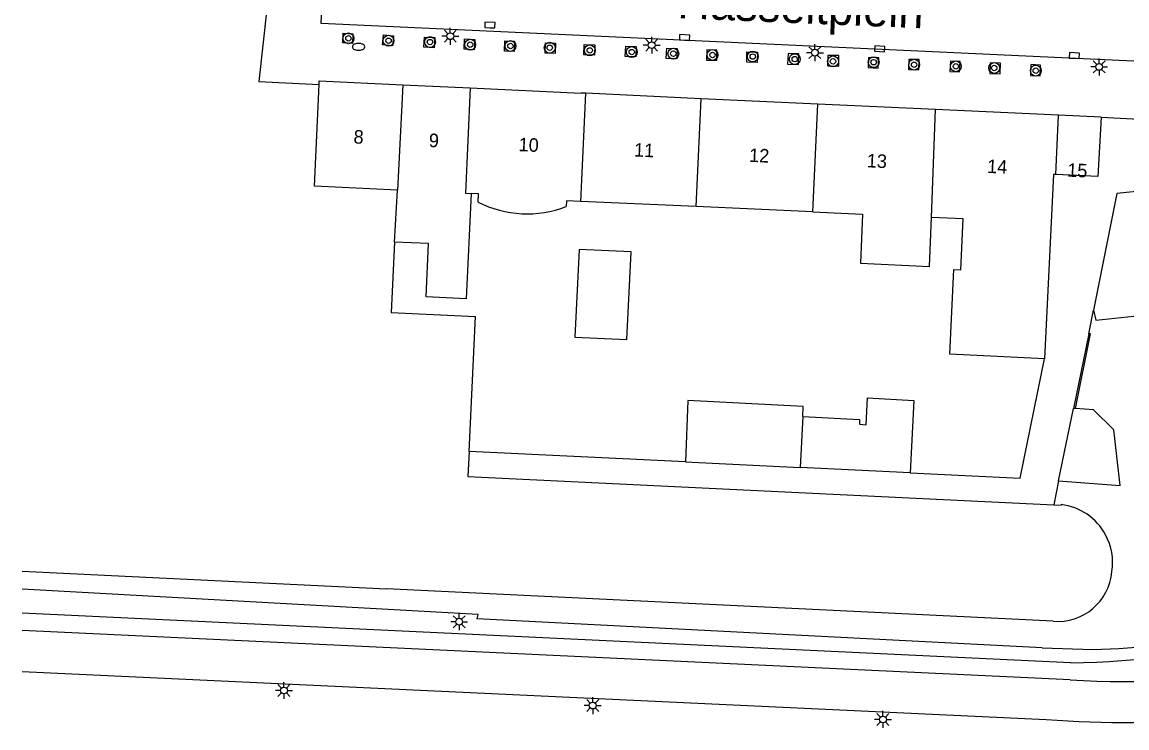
# Model space of a CAD drawing. Extents: x 132573 to 132944, y 398226 to 398676.
# Drawn here: x 132573 to 132654.8, y 398568.4 to 398620.6 of the extents above; entities that cross this region are included whole.
import ezdxf

# ---------------------------------------------------------------- set-up
doc = ezdxf.new("R2010")
doc.units = 0
for name, color, linetype in [('gg-afsc-erfafscheiding', 7, 'Continuous'), ('gg-afsc-muur', 7, 'Continuous'), ('gg-anno-huisnummerreeks BGT', 7, 'Continuous'), ('gg-anno-openbare ruimte label', 7, 'Continuous'), ('gg-bbg-bijgebouw', 7, 'Continuous'), ('gg-bbg-gedigitaliseerde bebouwing', 7, 'Continuous'), ('gg-bbg-gedigitaliseerde bijgebouw', 7, 'Continuous'), ('gg-bbg-hoofdgebouw', 7, 'Continuous'), ('gg-bbg-tussenscheiding', 7, 'Continuous'), ('gg-knt-verharding', 7, 'Continuous'), ('gt-grn-groengrens', 7, 'Continuous'), ('gt-grn-vlakafsluiter', 7, 'Continuous'), ('gt-symb-boom', 7, 'Continuous'), ('gt-symb-brandkraan', 7, 'Continuous'), ('gt-symb-kolk', 7, 'Continuous'), ('gt-symb-lichtmast', 7, 'Continuous')]:
    doc.layers.add(name, color=color, linetype=linetype)

msp = doc.modelspace()

# ---------------------------------------------------------------- linework, layer by layer
at = {"layer": 'gg-afsc-erfafscheiding'}
for p, q in [((132622.111, 398588.083), (132606.091, 398588.856)), ((132649.706, 398586.678), (132649.343, 398584.902))]:
    msp.add_line(p, q, dxfattribs=at)
msp.add_lwpolyline([(132638.715, 398587.282), (132646.87, 398586.889), (132648.673, 398595.704)], dxfattribs=at)
at = {"layer": 'gg-afsc-muur'}
msp.add_line((132651.936, 398597.566), (132650.802, 398592.037), dxfattribs=at)
msp.add_lwpolyline([(132650.955, 398592.027), (132652.078, 398597.554), (132651.936, 398597.566)], dxfattribs=at)
at = {"layer": 'gg-bbg-bijgebouw'}
for p, q in [((132652.868, 398613.57), (132649.703, 398613.717)), ((132649.706, 398586.678), (132650.802, 398592.037))]:
    msp.add_line(p, q, dxfattribs=at)
msp.add_lwpolyline([(132652.868, 398613.57), (132652.606, 398609.193), (132649.499, 398609.34)], dxfattribs=at)
at = {"layer": 'gg-bbg-gedigitaliseerde bebouwing'}
for p, q in [((132622.886, 398606.964), (132614.354, 398607.354)), ((132631.527, 398606.569), (132622.886, 398606.964)), ((132642.649, 398606.061), (132640.296, 398606.168)), ((132603.1, 398604.224), (132600.586, 398604.342))]:
    msp.add_line(p, q, dxfattribs=at)
for points in [[(132606.24, 398607.932), (132605.878, 398600.155), (132602.917, 398600.293), (132603.1, 398604.224)], [(132606.753, 398607.302), (132606.781, 398607.907), (132606.24, 398607.932)], [(132614.354, 398607.354), (132613.305, 398607.401), (132613.285, 398606.973)], [(132631.527, 398606.569), (132635.204, 398606.401), (132635.059, 398602.782), (132640.156, 398602.545), (132640.296, 398606.168)], [(132600.586, 398604.342), (132600.317, 398599.137), (132606.573, 398598.846)], [(132652.459, 398598.564), (132659.972, 398599.355), (132660.356, 398602.416), (132665.886, 398602.997), (132665.967, 398602.229), (132666.105, 398602.244)]]:
    msp.add_lwpolyline(points, dxfattribs=at)
msp.add_arc((132610.385, 398614.402), 7.975, 242.90768, 291.32552, dxfattribs=at)
at = {"layer": 'gg-bbg-gedigitaliseerde bijgebouw'}
for p, q in [((132650.955, 398592.027), (132650.802, 398592.037)), ((132622.111, 398588.083), (132630.578, 398587.675)), ((132638.715, 398587.282), (132630.578, 398587.675))]:
    msp.add_line(p, q, dxfattribs=at)
for points in [[(132613.923, 398597.308), (132617.769, 398597.123), (132618.082, 398603.615), (132614.236, 398603.8), (132613.923, 398597.308)], [(132630.777, 398591.447), (132630.815, 398592.169), (132622.286, 398592.617), (132622.111, 398588.083)], [(132630.777, 398591.447), (132634.987, 398591.225), (132634.968, 398590.86), (132635.471, 398590.833), (132635.575, 398592.809), (132638.996, 398592.63), (132638.715, 398587.282)], [(132649.706, 398586.678), (132654.253, 398586.339), (132653.79, 398590.46), (132652.281, 398591.936), (132650.955, 398592.027)]]:
    msp.add_lwpolyline(points, dxfattribs=at)
at = {"layer": 'gg-bbg-hoofdgebouw'}
for p, q in [((132601.19, 398615.973), (132606.182, 398615.741)), ((132606.182, 398615.741), (132614.395, 398615.36)), ((132614.725, 398615.345), (132614.395, 398615.36)), ((132623.257, 398614.948), (132614.725, 398615.345)), ((132631.897, 398614.546), (132623.257, 398614.948)), ((132640.605, 398614.141), (132631.897, 398614.546)), ((132649.703, 398613.717), (132640.605, 398614.141)), ((132654.024, 398607.93), (132652.286, 398599.3)), ((132606.091, 398588.856), (132606.573, 398598.846)), ((132652.286, 398599.3), (132652.459, 398598.564)), ((132649.343, 398584.902), (132649.886, 398584.876)), ((132649.89, 398584.926), (132649.886, 398584.876)), ((132573.021, 398579.988), (132599.98, 398578.68)), ((132649.31, 398576.29), (132599.98, 398578.68))]:
    msp.add_line(p, q, dxfattribs=at)
for points in [[(132591.13, 398621.59), (132590.53, 398616.21), (132595, 398616)], [(132595, 398616), (132594.99, 398616.26), (132601.19, 398615.973)], [(132658.72, 398611.67), (132659.07, 398608.45), (132654.024, 398607.93)], [(132649.499, 398609.34), (132649.322, 398609.348), (132648.673, 398595.704)], [(132648.673, 398595.704), (132641.657, 398596.048), (132641.965, 398602.32), (132642.464, 398602.296), (132642.649, 398606.061)], [(132606.091, 398588.856), (132606.001, 398586.992), (132649.343, 398584.902)]]:
    msp.add_lwpolyline(points, dxfattribs=at)
for centre, radius, start, end in [((132649.379, 398580.631), 4.325, 28.41018, 83.21173), ((132649.382, 398580.634), 4.321, 351.18938, 28.39803), ((132649.634, 398580.309), 4.032, 265.39185, 355.20379)]:
    msp.add_arc(centre, radius, start, end, dxfattribs=at)
at = {"layer": 'gg-bbg-tussenscheiding'}
for p, q in [((132601.19, 398615.973), (132600.784, 398608.187)), ((132614.354, 398607.354), (132614.725, 398615.345)), ((132622.886, 398606.964), (132623.257, 398614.948)), ((132631.527, 398606.569), (132631.897, 398614.546)), ((132640.296, 398606.168), (132640.605, 398614.141)), ((132649.499, 398609.34), (132649.703, 398613.717)), ((132600.586, 398604.342), (132600.784, 398608.187)), ((132630.777, 398591.447), (132630.578, 398587.675))]:
    msp.add_line(p, q, dxfattribs=at)
for points in [[(132600.784, 398608.187), (132594.647, 398608.471), (132595, 398616)], [(132606.182, 398615.741), (132605.821, 398607.952), (132606.24, 398607.932)]]:
    msp.add_lwpolyline(points, dxfattribs=at)
at = {"layer": 'gg-knt-verharding'}
for p, q in [((132652.868, 398613.57), (132658.543, 398613.295)), ((132650.6, 398573.223), (132573.021, 398576.899)), ((132650.56, 398571.965), (132573.021, 398575.616)), ((132573.021, 398572.575), (132648.794, 398569.03))]:
    msp.add_line(p, q, dxfattribs=at)
for points in [[(132662.19, 398617.41), (132595.15, 398620.52), (132595.275, 398623.27)], [(132596.75, 398619.066), (132596.777, 398619.788), (132597.492, 398619.755), (132597.459, 398619.033), (132596.75, 398619.066)], [(132599.698, 398618.925), (132599.766, 398619.658), (132600.492, 398619.591), (132600.424, 398618.858), (132599.698, 398618.925)], [(132602.748, 398618.752), (132602.787, 398619.503), (132603.553, 398619.472), (132603.503, 398618.713), (132602.748, 398618.752)], [(132605.734, 398618.618), (132605.757, 398619.363), (132606.519, 398619.335), (132606.467, 398618.568), (132605.734, 398618.618)], [(132608.701, 398618.468), (132608.744, 398619.234), (132609.448, 398619.195), (132609.439, 398618.427), (132608.701, 398618.468)], [(132611.719, 398618.302), (132611.736, 398619.08), (132612.497, 398619.051), (132612.463, 398618.286), (132611.719, 398618.302)], [(132614.594, 398618.187), (132614.602, 398618.946), (132615.384, 398618.923), (132615.375, 398618.163), (132614.594, 398618.187)], [(132617.629, 398618.06), (132617.68, 398618.831), (132618.443, 398618.803), (132618.43, 398618.046), (132617.629, 398618.06)], [(132620.666, 398617.923), (132620.721, 398618.677), (132621.491, 398618.668), (132621.451, 398617.883), (132620.666, 398617.923)], [(132623.679, 398618.56), (132623.646, 398617.806), (132624.414, 398617.799), (132624.421, 398618.526), (132623.679, 398618.56)], [(132626.645, 398618.421), (132627.423, 398618.392), (132627.409, 398617.625), (132626.631, 398617.659), (132626.645, 398618.421)], [(132629.707, 398618.294), (132629.653, 398617.509), (132630.467, 398617.485), (132630.484, 398618.274), (132629.707, 398618.294)], [(132632.637, 398618.149), (132632.62, 398617.383), (132633.447, 398617.358), (132633.454, 398618.137), (132632.637, 398618.149)], [(132635.645, 398617.993), (132635.611, 398617.254), (132636.365, 398617.202), (132636.403, 398617.963), (132635.645, 398617.993)], [(132638.631, 398617.857), (132638.596, 398617.11), (132639.359, 398617.081), (132639.387, 398617.854), (132638.631, 398617.857)], [(132641.707, 398617.715), (132641.652, 398616.962), (132642.387, 398616.93), (132642.414, 398617.708), (132641.707, 398617.715)], [(132644.636, 398617.591), (132644.621, 398616.813), (132645.377, 398616.788), (132645.404, 398617.579), (132644.636, 398617.591)], [(132647.629, 398616.656), (132648.355, 398616.641), (132648.378, 398617.43), (132647.646, 398617.469), (132647.629, 398616.656)]]:
    msp.add_lwpolyline(points, dxfattribs=at)
for centre, radius, start, end in [((132649.817, 398635.89), 62.672, 270.71597, 284.60424), ((132654.857, 398641.739), 69.906, 266.47629, 279.41239), ((132654.44, 398639.105), 70.302, 265.39395, 286.4367)]:
    msp.add_arc(centre, radius, start, end, dxfattribs=at)
at = {"layer": 'gt-grn-groengrens'}
msp.add_line((132648.494, 398574.318), (132652.233, 398574.203), dxfattribs=at)
msp.add_lwpolyline([(132648.494, 398574.318), (132606.702, 398576.468), (132606.764, 398576.802), (132573.021, 398578.675)], dxfattribs=at)
msp.add_arc((132651.678, 398614.585), 40.385, 270.78693, 285.37212, dxfattribs=at)
at = {"layer": 'gt-grn-vlakafsluiter'}
msp.add_line((132651.936, 398597.566), (132652.286, 398599.3), dxfattribs=at)
at = {"layer": 'gt-symb-boom'}
for centre, radius in [((132597.162, 398619.412), 0.4), ((132597.162, 398619.412), 0.2), ((132600.135, 398619.235), 0.4), ((132600.135, 398619.235), 0.2), ((132603.201, 398619.136), 0.4), ((132603.201, 398619.136), 0.2), ((132606.177, 398618.941), 0.4), ((132606.177, 398618.941), 0.2), ((132609.15, 398618.845), 0.4), ((132609.15, 398618.845), 0.2), ((132612.057, 398618.716), 0.4), ((132612.057, 398618.716), 0.2), ((132615.019, 398618.52), 0.4), ((132615.019, 398618.52), 0.2), ((132618.125, 398618.397), 0.4), ((132618.125, 398618.397), 0.2), ((132621.204, 398618.275), 0.4), ((132621.204, 398618.275), 0.2), ((132624.102, 398618.18), 0.4), ((132627.082, 398618.064), 0.4), ((132624.102, 398618.18), 0.2), ((132627.082, 398618.064), 0.2), ((132630.185, 398617.874), 0.4), ((132630.185, 398617.874), 0.2), ((132633.019, 398617.708), 0.4), ((132633.019, 398617.708), 0.2), ((132636.025, 398617.643), 0.4), ((132636.025, 398617.643), 0.2), ((132639.019, 398617.463), 0.4), ((132639.019, 398617.463), 0.2), ((132642.105, 398617.339), 0.4), ((132642.105, 398617.339), 0.2), ((132644.949, 398617.216), 0.4), ((132644.949, 398617.216), 0.2), ((132648.017, 398617.022), 0.4), ((132648.017, 398617.022), 0.2)]:
    msp.add_circle(centre, radius, dxfattribs=at)
at = {"layer": 'gt-symb-brandkraan'}
for centre, radius, start, end in [((132597.673, 398618.785), 0.206, 107.56694, 252.43307), ((132598.516, 398616.121), 3, 106.89205, 107.56694), ((132598.516, 398621.449), 3, 252.43307, 253.10797), ((132597.917, 398618.094), 0.938, 73.10799, 106.89205), ((132597.917, 398619.476), 0.938, 253.10797, 286.89206), ((132597.318, 398616.121), 3, 72.43309, 73.10799), ((132597.318, 398621.449), 3, 286.89206, 287.56695), ((132598.161, 398618.785), 0.206, 287.56695, 72.43309)]:
    msp.add_arc(centre, radius, start, end, dxfattribs=at)
at = {"layer": 'gt-symb-kolk'}
for points in [[(132607.62, 398620.193), (132607.995, 398620.176), (132608.013, 398620.576), (132607.263, 398620.609), (132607.245, 398620.21), (132607.62, 398620.193)], [(132622.025, 398619.273), (132622.4, 398619.255), (132622.419, 398619.654), (132621.67, 398619.691), (132621.65, 398619.291), (132622.025, 398619.273)], [(132636.478, 398618.831), (132636.103, 398618.849), (132636.084, 398618.45), (132636.833, 398618.413), (132636.853, 398618.813), (132636.478, 398618.831)], [(132650.862, 398617.936), (132651.237, 398617.918), (132651.255, 398618.318), (132650.506, 398618.353), (132650.487, 398617.954), (132650.862, 398617.936)]]:
    msp.add_lwpolyline(points, dxfattribs=at)
at = {"layer": 'gt-symb-lichtmast'}
for p, q in [((132604.704, 398619.817), (132604.704, 398620.192)), ((132604.454, 398619.567), (132604.079, 398619.567)), ((132604.527, 398619.744), (132604.262, 398620.009)), ((132604.527, 398619.39), (132604.262, 398619.125)), ((132604.704, 398619.317), (132604.704, 398618.942)), ((132604.881, 398619.744), (132605.146, 398620.009)), ((132605.146, 398619.125), (132604.881, 398619.39)), ((132604.954, 398619.567), (132605.329, 398619.567)), ((132619.425, 398619.08), (132619.16, 398619.345)), ((132619.602, 398619.153), (132619.602, 398619.528)), ((132619.779, 398619.08), (132620.044, 398619.345)), ((132619.352, 398618.903), (132618.977, 398618.903)), ((132619.425, 398618.726), (132619.16, 398618.461)), ((132619.602, 398618.653), (132619.602, 398618.278)), ((132620.044, 398618.461), (132619.779, 398618.726)), ((132619.852, 398618.903), (132620.227, 398618.903)), ((132631.502, 398618.527), (132631.237, 398618.792)), ((132631.679, 398618.6), (132631.679, 398618.975)), ((132631.856, 398618.527), (132632.121, 398618.792)), ((132631.429, 398618.35), (132631.054, 398618.35)), ((132631.502, 398618.173), (132631.237, 398617.908)), ((132631.679, 398618.1), (132631.679, 398617.725)), ((132632.121, 398617.908), (132631.856, 398618.173)), ((132631.929, 398618.35), (132632.304, 398618.35)), ((132652.532, 398617.472), (132652.267, 398617.737)), ((132652.709, 398617.545), (132652.709, 398617.92)), ((132652.886, 398617.472), (132653.151, 398617.737)), ((132652.459, 398617.295), (132652.084, 398617.295)), ((132652.532, 398617.118), (132652.267, 398616.853)), ((132652.709, 398617.045), (132652.709, 398616.67)), ((132653.151, 398616.853), (132652.886, 398617.118)), ((132652.959, 398617.295), (132653.334, 398617.295)), ((132605.357, 398576.511), (132605.357, 398576.886)), ((132605.107, 398576.261), (132604.732, 398576.261)), ((132605.18, 398576.438), (132604.915, 398576.703)), ((132605.18, 398576.084), (132604.915, 398575.819)), ((132605.357, 398576.011), (132605.357, 398575.636)), ((132605.534, 398576.438), (132605.799, 398576.703)), ((132605.799, 398575.819), (132605.534, 398576.084)), ((132605.607, 398576.261), (132605.982, 398576.261)), ((132592.145, 398571.169), (132591.77, 398571.169)), ((132592.218, 398571.346), (132591.953, 398571.611)), ((132592.395, 398571.419), (132592.395, 398571.794)), ((132592.572, 398571.346), (132592.837, 398571.611)), ((132592.645, 398571.169), (132593.02, 398571.169)), ((132592.218, 398570.992), (132591.953, 398570.727)), ((132592.395, 398570.919), (132592.395, 398570.544)), ((132592.837, 398570.727), (132592.572, 398570.992)), ((132615.061, 398570.233), (132614.796, 398570.498)), ((132615.238, 398570.306), (132615.238, 398570.681)), ((132615.415, 398570.233), (132615.68, 398570.498)), ((132614.988, 398570.056), (132614.613, 398570.056)), ((132615.061, 398569.879), (132614.796, 398569.614)), ((132615.238, 398569.806), (132615.238, 398569.431)), ((132615.68, 398569.614), (132615.415, 398569.879)), ((132615.488, 398570.056), (132615.863, 398570.056)), ((132636.537, 398569.208), (132636.272, 398569.473)), ((132636.714, 398569.281), (132636.714, 398569.656)), ((132636.891, 398569.208), (132637.156, 398569.473)), ((132636.464, 398569.031), (132636.089, 398569.031)), ((132636.537, 398568.854), (132636.272, 398568.589)), ((132636.714, 398568.781), (132636.714, 398568.406)), ((132637.156, 398568.589), (132636.891, 398568.854)), ((132636.964, 398569.031), (132637.339, 398569.031))]:
    msp.add_line(p, q, dxfattribs=at)
for centre in [(132604.704, 398619.567), (132619.602, 398618.903), (132631.679, 398618.35), (132652.709, 398617.295), (132605.357, 398576.261), (132592.395, 398571.169), (132615.238, 398570.056), (132636.714, 398569.031)]:
    msp.add_circle(centre, 0.25, dxfattribs=at)

# ---------------------------------------------------------------- texts
at = {"layer": 'gg-anno-huisnummerreeks BGT'}
for s, rotation, p in [('8', 357.3, (132597.525, 398611.639)), ('9', 357.4, (132603.097, 398611.379)), ('10', 357.4, (132609.739, 398611.071)), ('11', 357.4, (132618.28, 398610.674)), ('12', 357.4, (132626.797, 398610.279)), ('13', 357.4, (132635.498, 398609.874)), ('14', 357.3, (132644.403, 398609.46)), ('15', 357.3, (132650.329, 398609.184))]:
    msp.add_text(s, height=1, rotation=rotation, dxfattribs=at).set_placement(p)
at = {"layer": 'gg-anno-openbare ruimte label'}
msp.add_text('Hasseltplein', height=2.5, rotation=357.6, dxfattribs=at).set_placement((132621.482, 398620.912))

doc.saveas('drawing.dxf')
